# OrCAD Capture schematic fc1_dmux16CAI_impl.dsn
size A
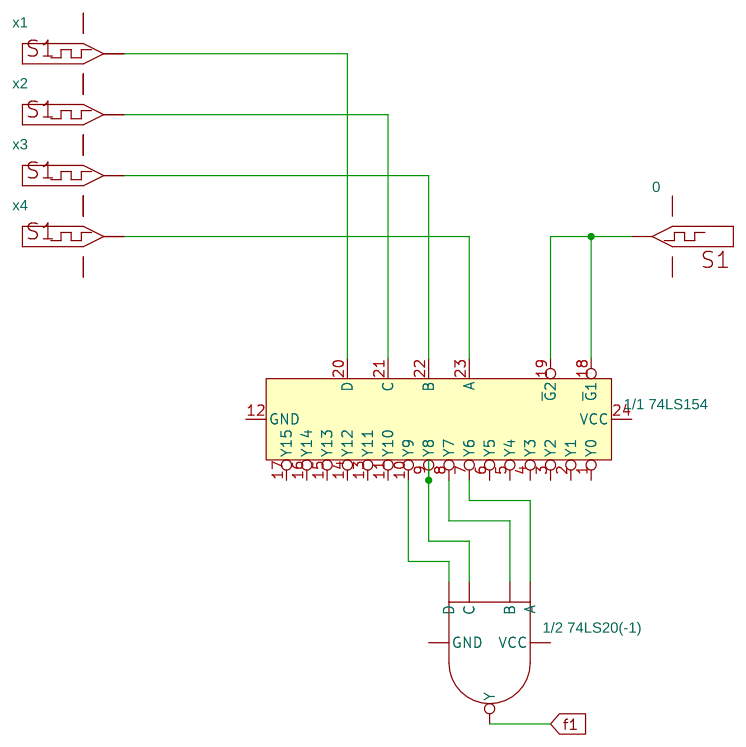
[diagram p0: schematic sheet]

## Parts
0  DigStim1
U1  1/1 74LS154  [DIP.100/24/W.300/L1.250]
U3  1/2 74LS20(-1)  [DIP.100/14/W.300/L.800]  (section A)
x1  DigStim1
x2  DigStim1
x3  DigStim1
x4  DigStim1

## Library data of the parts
0 x1-x4 = DigStim1
U1 = 74154
U3 = 74LS20

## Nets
GND: 0.3(GND) U1.12(GND) U3.7(GND) x1.3(GND) x2.3(GND) x3.3(GND) x4.3(GND)
VCC: 0.2(VCC) U1.24(VCC) U3.14(VCC) x1.2(VCC) x2.2(VCC) x3.2(VCC) x4.2(VCC)
f1: U3.6(Y)
N16248: 0.OUT U1.18(~{G}1) U1.19(~{G}2)
N16266: U1.23(A) x4.OUT
N16276: U1.22(B) x3.OUT
N16286: U1.21(C) x2.OUT
N16296: U1.20(D) x1.OUT
N16344: U1.7(Y6) U3.1(A)
N16358: U1.8(Y7) U3.2(B)
N16372: U1.9(Y8) U3.4(C)
N16390: U1.10(Y9) U3.5(D)

Not connected (* = marked no-connect by the designer): U1 1(Y0) 2(Y1) 3(Y2) 4(Y3) 5(Y4) 6(Y5) 11(Y10) 13(Y11) 14(Y12) 15(Y13) 16(Y14) 17(Y15)
